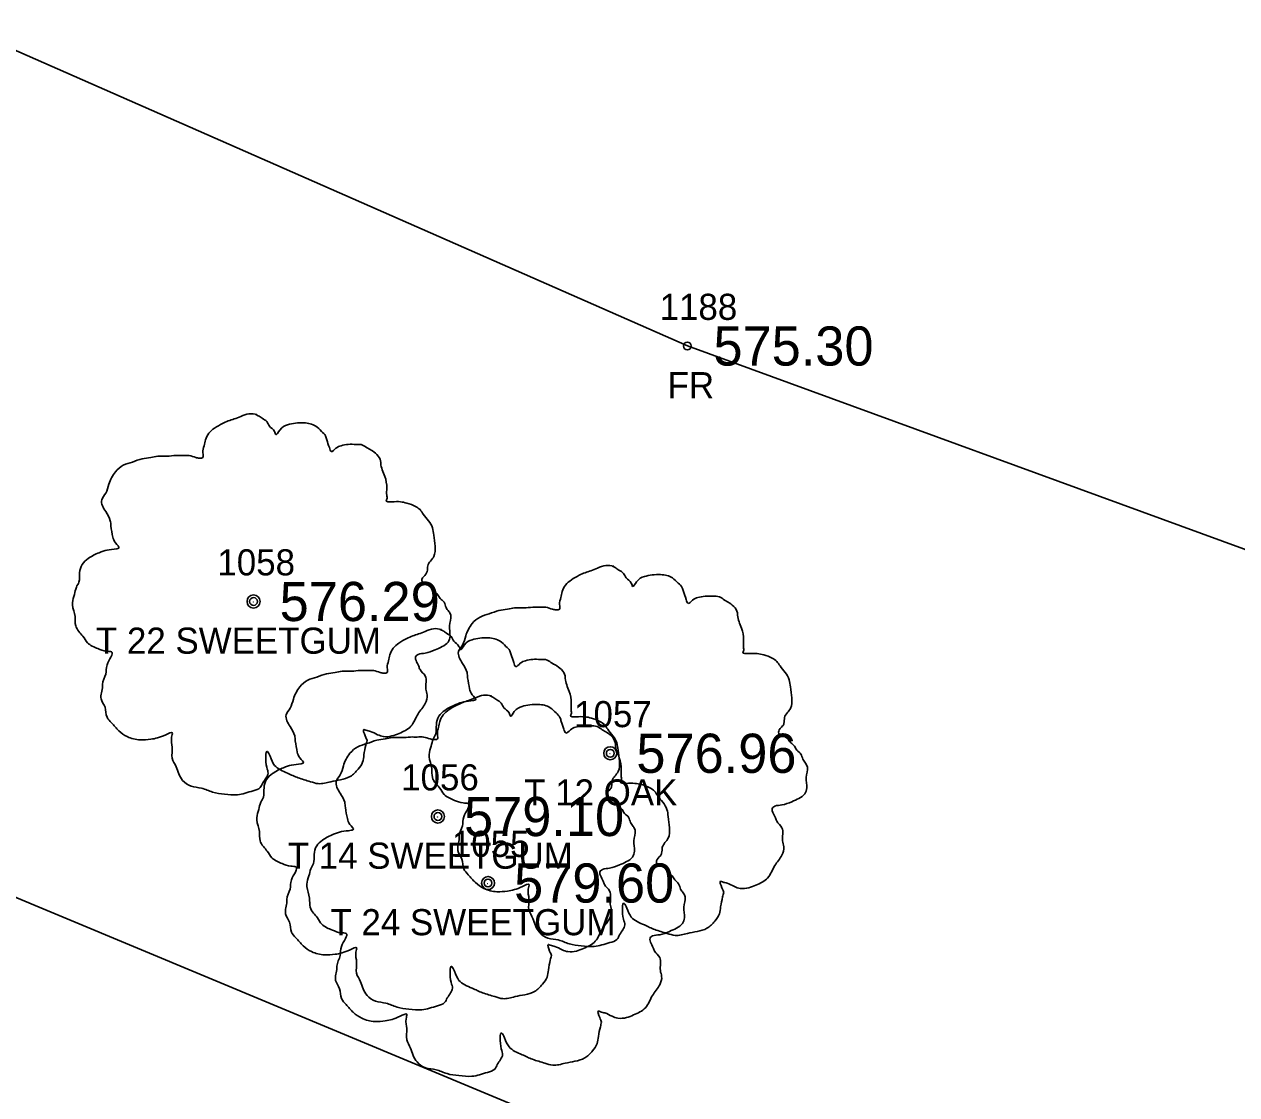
# Model space of a CAD drawing. Extents: x 1664393 to 1667175, y 987029 to 988607.
# Drawn here: x 1665718.92 to 1665765.38, y 987677.54 to 987718.55 of the extents above; entities that cross this region are included whole.
import ezdxf

# ---------------------------------------------------------------- set-up
doc = ezdxf.new("R2010")
doc.units = 0
for name, color, linetype in [('RD_EX_Fence_Other', 7, 'Continuous'), ('RD_EX_Fence_Other_txCode', 7, 'Continuous'), ('RD_EX_Road', 7, 'Continuous'), ('RD_EX_TX_Fence_Other_ELEV', 7, 'Continuous'), ('RD_EX_TX_VEG_ELEV', 7, 'Continuous'), ('RD_EX_VEG', 7, 'Continuous'), ('RD_EX_VEG_txCode', 7, 'Continuous'), ('RD_SMD_Locator', 7, 'Continuous')]:
    doc.layers.add(name, color=color, linetype=linetype)

msp = doc.modelspace()

# ---------------------------------------------------------------- linework, layer by layer
at = {"layer": 'RD_EX_Fence_Other'}
msp.add_lwpolyline([(1666177.674, 987530.312), (1666129.013, 987549.765), (1665988.605, 987609.559), (1665898.393, 987649.997), (1665744.328, 987706.222), (1665608.989, 987765.723), (1665620.073, 987798.185), (1665636.547, 987846.221)], dxfattribs=at)
at = {"layer": 'RD_EX_Road'}
msp.add_lwpolyline([(1666163.185, 987497.623), (1666116.595, 987517.386), (1666070.703, 987536.94), (1666024.42, 987556.434), (1665979.015, 987575.668), (1665932.354, 987595.551), (1665886.935, 987614.539), (1665839.872, 987634.254), (1665794.504, 987653.269), (1665748.805, 987672.511), (1665702.363, 987691.865), (1665656.419, 987711.451), (1665610.33, 987731.033), (1665564.854, 987750.933), (1665531.474, 987764.82)], dxfattribs=at)
at = {"layer": 'RD_EX_VEG'}
for centre, radius in [((1665727.705, 987696.435), 0.25), ((1665727.693, 987696.416), 0.0001), ((1665741.375, 987690.621), 0.25), ((1665741.363, 987690.602), 0.0001), ((1665734.771, 987688.199), 0.25), ((1665734.759, 987688.18), 0.0001), ((1665736.69, 987685.651), 0.25), ((1665736.678, 987685.632), 0.0001)]:
    msp.add_circle(centre, radius, dxfattribs=at)
for points in [[(1665727.837, 987703.602), (1665727.537, 987703.627), (1665727.213, 987703.527), (1665726.963, 987703.427), (1665726.738, 987703.352), (1665726.513, 987703.252), (1665726.213, 987703.078), (1665725.988, 987702.878), (1665725.863, 987702.628), (1665725.813, 987702.403), (1665725.763, 987702.128), (1665725.763, 987701.953), (1665725.638, 987701.928), (1665725.488, 987701.953), (1665725.238, 987702.028), (1665724.988, 987702.028), (1665724.739, 987702.028), (1665724.389, 987702.003), (1665724.039, 987702.003), (1665723.764, 987701.953), (1665723.439, 987701.903), (1665723.064, 987701.778), (1665722.714, 987701.653), (1665722.415, 987701.403), (1665722.165, 987700.928), (1665722.04, 987700.579), (1665721.89, 987700.329), (1665722.04, 987699.879), (1665722.215, 987699.529), (1665722.24, 987699.329), (1665722.315, 987698.904), (1665722.415, 987698.679), (1665722.54, 987698.479), (1665722.465, 987698.455), (1665722.09, 987698.405), (1665721.79, 987698.305), (1665721.365, 987698.08), (1665721.14, 987697.855), (1665721.04, 987697.53), (1665721.015, 987697.18), (1665720.915, 987696.98), (1665720.84, 987696.705), (1665720.815, 987696.63), (1665720.765, 987696.305), (1665720.865, 987695.856), (1665720.89, 987695.506), (1665721.015, 987695.281), (1665721.165, 987695.106), (1665721.34, 987694.856), (1665721.74, 987694.631), (1665722.065, 987694.531), (1665722.265, 987694.506), (1665722.09, 987694.006), (1665722.04, 987693.657), (1665721.915, 987693.257), (1665721.915, 987693.182), (1665721.865, 987692.707), (1665722.015, 987692.382), (1665722.09, 987692.007), (1665722.265, 987691.782), (1665722.54, 987691.483), (1665722.864, 987691.258), (1665723.364, 987691.133), (1665723.764, 987691.158), (1665724.339, 987691.333), (1665724.589, 987691.408), (1665724.564, 987691.233), (1665724.589, 987690.858), (1665724.589, 987690.433), (1665724.739, 987690.108), (1665724.839, 987689.833), (1665724.988, 987689.583), (1665725.313, 987689.359), (1665725.713, 987689.284), (1665726.138, 987689.134), (1665726.588, 987689.059), (1665727.088, 987689.034), (1665727.687, 987689.184), (1665727.962, 987689.309), (1665728.062, 987689.483), (1665728.262, 987689.858), (1665728.212, 987690.083), (1665728.237, 987690.683), (1665728.337, 987690.508), (1665728.512, 987690.158), (1665729.012, 987689.858), (1665729.412, 987689.683), (1665729.886, 987689.533), (1665730.186, 987689.458), (1665730.661, 987689.533), (1665731.036, 987689.608), (1665731.411, 987689.733), (1665731.711, 987690.008), (1665731.885, 987690.283), (1665731.935, 987690.558), (1665732.01, 987690.933), (1665732.06, 987691.108)], [(1665732.06, 987691.108), (1665731.985, 987691.283), (1665731.935, 987691.533), (1665732.01, 987691.508), (1665732.185, 987691.458), (1665732.46, 987691.333), (1665732.685, 987691.258), (1665733.01, 987691.283), (1665733.285, 987691.383), (1665733.735, 987691.658), (1665734.01, 987692.132), (1665734.284, 987692.532), (1665734.359, 987692.857), (1665734.309, 987693.082), (1665734.284, 987693.582), (1665734.084, 987693.832), (1665734.034, 987693.956), (1665733.935, 987694.356), (1665734.01, 987694.406), (1665734.284, 987694.456), (1665734.659, 987694.581), (1665734.934, 987694.706), (1665735.159, 987694.881), (1665735.234, 987695.106), (1665735.209, 987695.506), (1665735.259, 987695.906), (1665735.184, 987696.056), (1665735.084, 987696.205), (1665735.009, 987696.405), (1665734.859, 987696.555), (1665734.759, 987696.705), (1665734.659, 987696.805), (1665734.534, 987696.955), (1665734.359, 987697.08), (1665734.209, 987697.13), (1665734.159, 987697.28), (1665734.309, 987697.48), (1665734.359, 987697.58), (1665734.384, 987697.805), (1665734.609, 987698.155), (1665734.659, 987698.554), (1665734.609, 987698.979), (1665734.559, 987699.254), (1665734.409, 987699.529), (1665734.209, 987699.779), (1665734.084, 987699.954), (1665733.91, 987700.079), (1665733.585, 987700.204), (1665733.335, 987700.254), (1665732.985, 987700.254), (1665732.785, 987700.304), (1665732.81, 987700.354), (1665732.81, 987700.504), (1665732.81, 987700.779), (1665732.735, 987701.228), (1665732.585, 987701.728), (1665732.585, 987701.753), (1665732.485, 987702.003), (1665732.26, 987702.203), (1665732.085, 987702.303), (1665731.885, 987702.428), (1665731.636, 987702.453), (1665731.336, 987702.453), (1665731.061, 987702.403), (1665730.861, 987702.303), (1665730.686, 987702.178), (1665730.611, 987702.328), (1665730.511, 987702.628), (1665730.461, 987702.778), (1665730.311, 987702.953), (1665730.086, 987703.152), (1665729.636, 987703.277), (1665729.012, 987703.202), (1665728.712, 987703.003), (1665728.562, 987702.828), (1665728.512, 987702.953), (1665728.312, 987703.152), (1665728.212, 987703.327), (1665728.037, 987703.452), (1665727.887, 987703.552), (1665727.787, 987703.602)], [(1665741.507, 987697.788), (1665741.207, 987697.813), (1665740.883, 987697.713), (1665740.633, 987697.613), (1665740.408, 987697.538), (1665740.183, 987697.438), (1665739.883, 987697.263), (1665739.658, 987697.063), (1665739.533, 987696.813), (1665739.483, 987696.588), (1665739.433, 987696.314), (1665739.433, 987696.139), (1665739.308, 987696.114), (1665739.158, 987696.139), (1665738.908, 987696.214), (1665738.658, 987696.214), (1665738.409, 987696.214), (1665738.059, 987696.189), (1665737.709, 987696.189), (1665737.434, 987696.139), (1665737.109, 987696.089), (1665736.734, 987695.964), (1665736.384, 987695.839), (1665736.085, 987695.589), (1665735.835, 987695.114), (1665735.71, 987694.764), (1665735.56, 987694.514), (1665735.71, 987694.065), (1665735.885, 987693.715), (1665735.91, 987693.515), (1665735.985, 987693.09), (1665736.085, 987692.865), (1665736.21, 987692.665), (1665736.135, 987692.64), (1665735.76, 987692.59), (1665735.46, 987692.49), (1665735.035, 987692.265), (1665734.81, 987692.04), (1665734.71, 987691.715), (1665734.685, 987691.366), (1665734.585, 987691.166), (1665734.51, 987690.891), (1665734.485, 987690.816), (1665734.435, 987690.491), (1665734.535, 987690.041), (1665734.56, 987689.691), (1665734.685, 987689.466), (1665734.835, 987689.292), (1665735.01, 987689.042), (1665735.41, 987688.817), (1665735.735, 987688.717), (1665735.935, 987688.692), (1665735.76, 987688.192), (1665735.71, 987687.842), (1665735.585, 987687.442), (1665735.585, 987687.367), (1665735.535, 987686.893), (1665735.685, 987686.568), (1665735.76, 987686.193), (1665735.935, 987685.968), (1665736.21, 987685.668), (1665736.534, 987685.443), (1665737.034, 987685.318), (1665737.434, 987685.343), (1665738.009, 987685.518), (1665738.259, 987685.593), (1665738.234, 987685.418), (1665738.259, 987685.043), (1665738.259, 987684.619), (1665738.409, 987684.294), (1665738.509, 987684.019), (1665738.658, 987683.769), (1665738.983, 987683.544), (1665739.383, 987683.469), (1665739.808, 987683.319), (1665740.258, 987683.244), (1665740.758, 987683.219), (1665741.357, 987683.369), (1665741.632, 987683.494), (1665741.732, 987683.669), (1665741.932, 987684.044), (1665741.882, 987684.269), (1665741.907, 987684.869), (1665742.007, 987684.694), (1665742.182, 987684.344), (1665742.682, 987684.044), (1665743.082, 987683.869), (1665743.556, 987683.719), (1665743.856, 987683.644), (1665744.331, 987683.719), (1665744.706, 987683.794), (1665745.081, 987683.919), (1665745.381, 987684.194), (1665745.555, 987684.469), (1665745.605, 987684.744), (1665745.68, 987685.118), (1665745.73, 987685.293)], [(1665745.73, 987685.293), (1665745.655, 987685.468), (1665745.605, 987685.718), (1665745.68, 987685.693), (1665745.855, 987685.643), (1665746.13, 987685.518), (1665746.355, 987685.443), (1665746.68, 987685.468), (1665746.955, 987685.568), (1665747.405, 987685.843), (1665747.68, 987686.318), (1665747.954, 987686.718), (1665748.029, 987687.043), (1665747.979, 987687.267), (1665747.954, 987687.767), (1665747.754, 987688.017), (1665747.704, 987688.142), (1665747.605, 987688.542), (1665747.68, 987688.592), (1665747.954, 987688.642), (1665748.329, 987688.767), (1665748.604, 987688.892), (1665748.829, 987689.067), (1665748.904, 987689.292), (1665748.879, 987689.691), (1665748.929, 987690.091), (1665748.854, 987690.241), (1665748.754, 987690.391), (1665748.679, 987690.591), (1665748.529, 987690.741), (1665748.429, 987690.891), (1665748.329, 987690.991), (1665748.204, 987691.141), (1665748.029, 987691.266), (1665747.879, 987691.316), (1665747.829, 987691.466), (1665747.979, 987691.666), (1665748.029, 987691.765), (1665748.054, 987691.99), (1665748.279, 987692.34), (1665748.329, 987692.74), (1665748.279, 987693.165), (1665748.229, 987693.44), (1665748.079, 987693.715), (1665747.879, 987693.965), (1665747.754, 987694.139), (1665747.58, 987694.264), (1665747.255, 987694.389), (1665747.005, 987694.439), (1665746.655, 987694.439), (1665746.455, 987694.489), (1665746.48, 987694.539), (1665746.48, 987694.689), (1665746.48, 987694.964), (1665746.405, 987695.414), (1665746.255, 987695.914), (1665746.255, 987695.939), (1665746.155, 987696.189), (1665745.93, 987696.388), (1665745.755, 987696.488), (1665745.555, 987696.613), (1665745.306, 987696.638), (1665745.006, 987696.638), (1665744.731, 987696.588), (1665744.531, 987696.488), (1665744.356, 987696.363), (1665744.281, 987696.513), (1665744.181, 987696.813), (1665744.131, 987696.963), (1665743.981, 987697.138), (1665743.756, 987697.338), (1665743.306, 987697.463), (1665742.682, 987697.388), (1665742.382, 987697.188), (1665742.232, 987697.013), (1665742.182, 987697.138), (1665741.982, 987697.338), (1665741.882, 987697.513), (1665741.707, 987697.638), (1665741.557, 987697.738), (1665741.457, 987697.788)], [(1665734.903, 987695.367), (1665734.603, 987695.392), (1665734.279, 987695.292), (1665734.029, 987695.192), (1665733.804, 987695.117), (1665733.579, 987695.017), (1665733.279, 987694.842), (1665733.054, 987694.642), (1665732.929, 987694.392), (1665732.879, 987694.167), (1665732.829, 987693.892), (1665732.829, 987693.717), (1665732.704, 987693.692), (1665732.554, 987693.717), (1665732.304, 987693.792), (1665732.055, 987693.792), (1665731.805, 987693.792), (1665731.455, 987693.767), (1665731.105, 987693.767), (1665730.83, 987693.717), (1665730.505, 987693.667), (1665730.13, 987693.542), (1665729.781, 987693.417), (1665729.481, 987693.167), (1665729.231, 987692.693), (1665729.106, 987692.343), (1665728.956, 987692.093), (1665729.106, 987691.643), (1665729.281, 987691.293), (1665729.306, 987691.093), (1665729.381, 987690.669), (1665729.481, 987690.444), (1665729.606, 987690.244), (1665729.531, 987690.219), (1665729.156, 987690.169), (1665728.856, 987690.069), (1665728.431, 987689.844), (1665728.206, 987689.619), (1665728.106, 987689.294), (1665728.081, 987688.944), (1665727.981, 987688.744), (1665727.906, 987688.47), (1665727.881, 987688.395), (1665727.831, 987688.07), (1665727.931, 987687.62), (1665727.956, 987687.27), (1665728.081, 987687.045), (1665728.231, 987686.87), (1665728.406, 987686.62), (1665728.806, 987686.395), (1665729.131, 987686.295), (1665729.331, 987686.271), (1665729.156, 987685.771), (1665729.106, 987685.421), (1665728.981, 987685.021), (1665728.981, 987684.946), (1665728.931, 987684.471), (1665729.081, 987684.146), (1665729.156, 987683.772), (1665729.331, 987683.547), (1665729.606, 987683.247), (1665729.93, 987683.022), (1665730.43, 987682.897), (1665730.83, 987682.922), (1665731.405, 987683.097), (1665731.655, 987683.172), (1665731.63, 987682.997), (1665731.655, 987682.622), (1665731.655, 987682.197), (1665731.805, 987681.872), (1665731.905, 987681.598), (1665732.055, 987681.348), (1665732.379, 987681.123), (1665732.779, 987681.048), (1665733.204, 987680.898), (1665733.654, 987680.823), (1665734.154, 987680.798), (1665734.753, 987680.948), (1665735.028, 987681.073), (1665735.128, 987681.248), (1665735.328, 987681.623), (1665735.278, 987681.847), (1665735.303, 987682.447), (1665735.403, 987682.272), (1665735.578, 987681.922), (1665736.078, 987681.623), (1665736.478, 987681.448), (1665736.952, 987681.298), (1665737.252, 987681.223), (1665737.727, 987681.298), (1665738.102, 987681.373), (1665738.477, 987681.498), (1665738.777, 987681.772), (1665738.952, 987682.047), (1665739.002, 987682.322), (1665739.076, 987682.697), (1665739.126, 987682.872)], [(1665739.126, 987682.872), (1665739.052, 987683.047), (1665739.002, 987683.297), (1665739.076, 987683.272), (1665739.251, 987683.222), (1665739.526, 987683.097), (1665739.751, 987683.022), (1665740.076, 987683.047), (1665740.351, 987683.147), (1665740.801, 987683.422), (1665741.076, 987683.897), (1665741.35, 987684.296), (1665741.425, 987684.621), (1665741.375, 987684.846), (1665741.35, 987685.346), (1665741.151, 987685.596), (1665741.101, 987685.721), (1665741.001, 987686.121), (1665741.076, 987686.171), (1665741.35, 987686.221), (1665741.725, 987686.345), (1665742, 987686.47), (1665742.225, 987686.645), (1665742.3, 987686.87), (1665742.275, 987687.27), (1665742.325, 987687.67), (1665742.25, 987687.82), (1665742.15, 987687.97), (1665742.075, 987688.17), (1665741.925, 987688.32), (1665741.825, 987688.47), (1665741.725, 987688.569), (1665741.6, 987688.719), (1665741.425, 987688.844), (1665741.276, 987688.894), (1665741.226, 987689.044), (1665741.375, 987689.244), (1665741.425, 987689.344), (1665741.45, 987689.569), (1665741.675, 987689.919), (1665741.725, 987690.319), (1665741.675, 987690.744), (1665741.625, 987691.018), (1665741.475, 987691.293), (1665741.276, 987691.543), (1665741.151, 987691.718), (1665740.976, 987691.843), (1665740.651, 987691.968), (1665740.401, 987692.018), (1665740.051, 987692.018), (1665739.851, 987692.068), (1665739.876, 987692.118), (1665739.876, 987692.268), (1665739.876, 987692.543), (1665739.801, 987692.993), (1665739.651, 987693.492), (1665739.651, 987693.517), (1665739.551, 987693.767), (1665739.326, 987693.967), (1665739.151, 987694.067), (1665738.952, 987694.192), (1665738.702, 987694.217), (1665738.402, 987694.217), (1665738.127, 987694.167), (1665737.927, 987694.067), (1665737.752, 987693.942), (1665737.677, 987694.092), (1665737.577, 987694.392), (1665737.527, 987694.542), (1665737.377, 987694.717), (1665737.152, 987694.917), (1665736.702, 987695.042), (1665736.078, 987694.967), (1665735.778, 987694.767), (1665735.628, 987694.592), (1665735.578, 987694.717), (1665735.378, 987694.917), (1665735.278, 987695.092), (1665735.103, 987695.217), (1665734.953, 987695.317), (1665734.853, 987695.367)], [(1665736.822, 987692.818), (1665736.522, 987692.843), (1665736.198, 987692.743), (1665735.948, 987692.643), (1665735.723, 987692.568), (1665735.498, 987692.468), (1665735.198, 987692.293), (1665734.973, 987692.093), (1665734.848, 987691.843), (1665734.798, 987691.618), (1665734.748, 987691.344), (1665734.748, 987691.169), (1665734.623, 987691.144), (1665734.473, 987691.169), (1665734.223, 987691.244), (1665733.974, 987691.244), (1665733.724, 987691.244), (1665733.374, 987691.219), (1665733.024, 987691.219), (1665732.749, 987691.169), (1665732.424, 987691.119), (1665732.049, 987690.994), (1665731.7, 987690.869), (1665731.4, 987690.619), (1665731.15, 987690.144), (1665731.025, 987689.794), (1665730.875, 987689.544), (1665731.025, 987689.095), (1665731.2, 987688.745), (1665731.225, 987688.545), (1665731.3, 987688.12), (1665731.4, 987687.895), (1665731.525, 987687.695), (1665731.45, 987687.67), (1665731.075, 987687.62), (1665730.775, 987687.52), (1665730.35, 987687.295), (1665730.125, 987687.07), (1665730.025, 987686.745), (1665730, 987686.396), (1665729.9, 987686.196), (1665729.825, 987685.921), (1665729.8, 987685.846), (1665729.75, 987685.521), (1665729.85, 987685.071), (1665729.875, 987684.721), (1665730, 987684.496), (1665730.15, 987684.322), (1665730.325, 987684.072), (1665730.725, 987683.847), (1665731.05, 987683.747), (1665731.25, 987683.722), (1665731.075, 987683.222), (1665731.025, 987682.872), (1665730.9, 987682.472), (1665730.9, 987682.397), (1665730.85, 987681.923), (1665731, 987681.598), (1665731.075, 987681.223), (1665731.25, 987680.998), (1665731.525, 987680.698), (1665731.849, 987680.473), (1665732.349, 987680.348), (1665732.749, 987680.373), (1665733.324, 987680.548), (1665733.574, 987680.623), (1665733.549, 987680.448), (1665733.574, 987680.073), (1665733.574, 987679.649), (1665733.724, 987679.324), (1665733.824, 987679.049), (1665733.974, 987678.799), (1665734.298, 987678.574), (1665734.698, 987678.499), (1665735.123, 987678.349), (1665735.573, 987678.274), (1665736.073, 987678.249), (1665736.672, 987678.399), (1665736.947, 987678.524), (1665737.047, 987678.699), (1665737.247, 987679.074), (1665737.197, 987679.299), (1665737.222, 987679.899), (1665737.322, 987679.724), (1665737.497, 987679.374), (1665737.997, 987679.074), (1665738.397, 987678.899), (1665738.871, 987678.749), (1665739.171, 987678.674), (1665739.646, 987678.749), (1665740.021, 987678.824), (1665740.396, 987678.949), (1665740.696, 987679.224), (1665740.871, 987679.499), (1665740.921, 987679.774), (1665740.995, 987680.148), (1665741.045, 987680.323)], [(1665741.045, 987680.323), (1665740.971, 987680.498), (1665740.921, 987680.748), (1665740.995, 987680.723), (1665741.17, 987680.673), (1665741.445, 987680.548), (1665741.67, 987680.473), (1665741.995, 987680.498), (1665742.27, 987680.598), (1665742.72, 987680.873), (1665742.995, 987681.348), (1665743.269, 987681.748), (1665743.344, 987682.073), (1665743.294, 987682.297), (1665743.269, 987682.797), (1665743.07, 987683.047), (1665743.02, 987683.172), (1665742.92, 987683.572), (1665742.995, 987683.622), (1665743.269, 987683.672), (1665743.644, 987683.797), (1665743.919, 987683.922), (1665744.144, 987684.097), (1665744.219, 987684.322), (1665744.194, 987684.721), (1665744.244, 987685.121), (1665744.169, 987685.271), (1665744.069, 987685.421), (1665743.994, 987685.621), (1665743.844, 987685.771), (1665743.744, 987685.921), (1665743.644, 987686.021), (1665743.519, 987686.171), (1665743.344, 987686.296), (1665743.195, 987686.346), (1665743.145, 987686.496), (1665743.294, 987686.696), (1665743.344, 987686.795), (1665743.369, 987687.02), (1665743.594, 987687.37), (1665743.644, 987687.77), (1665743.594, 987688.195), (1665743.544, 987688.47), (1665743.394, 987688.745), (1665743.195, 987688.995), (1665743.07, 987689.169), (1665742.895, 987689.294), (1665742.57, 987689.419), (1665742.32, 987689.469), (1665741.97, 987689.469), (1665741.77, 987689.519), (1665741.795, 987689.569), (1665741.795, 987689.719), (1665741.795, 987689.994), (1665741.72, 987690.444), (1665741.57, 987690.944), (1665741.57, 987690.969), (1665741.47, 987691.219), (1665741.245, 987691.418), (1665741.07, 987691.518), (1665740.871, 987691.643), (1665740.621, 987691.668), (1665740.321, 987691.668), (1665740.046, 987691.618), (1665739.846, 987691.518), (1665739.671, 987691.393), (1665739.596, 987691.543), (1665739.496, 987691.843), (1665739.446, 987691.993), (1665739.296, 987692.168), (1665739.071, 987692.368), (1665738.621, 987692.493), (1665737.997, 987692.418), (1665737.697, 987692.218), (1665737.547, 987692.043), (1665737.497, 987692.168), (1665737.297, 987692.368), (1665737.197, 987692.543), (1665737.022, 987692.668), (1665736.872, 987692.768), (1665736.772, 987692.818)]]:
    msp.add_spline(points, degree=3, dxfattribs=at)
at = {"layer": 'RD_SMD_Locator'}
for centre in [(1665744.328, 987706.222), (1665727.705, 987696.435), (1665741.375, 987690.621), (1665734.771, 987688.199), (1665736.69, 987685.651)]:
    msp.add_circle(centre, 0.15, dxfattribs=at)

# ---------------------------------------------------------------- texts
at = {"layer": 'RD_EX_Fence_Other_txCode'}
for s, p in [('1188', (1665743.265, 987707.222)), ('FR', (1665743.572, 987704.222))]:
    msp.add_text(s, height=1, dxfattribs=at).set_placement(p)
at = {"layer": 'RD_EX_TX_Fence_Other_ELEV'}
msp.add_text('575.30', height=1.5, dxfattribs=at).set_placement((1665745.328, 987705.472))
at = {"layer": 'RD_EX_TX_VEG_ELEV'}
for s, p in [('576.29', (1665728.705, 987695.685)), ('576.96', (1665742.375, 987689.871)), ('579.10', (1665735.771, 987687.449)), ('579.60', (1665737.69, 987684.901))]:
    msp.add_text(s, height=1.5, dxfattribs=at).set_placement(p)
at = {"layer": 'RD_EX_VEG_txCode'}
for s, p in [('1058', (1665726.319, 987697.435)), ('T 22 SWEETGUM', (1665721.666, 987694.435)), ('1057', (1665739.989, 987691.621)), ('1056', (1665733.362, 987689.199)), ('T 12 OAK', (1665738.076, 987688.621)), ('1055', (1665735.305, 987686.651)), ('T 14 SWEETGUM', (1665729.015, 987686.199)), ('T 24 SWEETGUM', (1665730.651, 987683.651))]:
    msp.add_text(s, height=1, dxfattribs=at).set_placement(p)

doc.saveas('drawing.dxf')
